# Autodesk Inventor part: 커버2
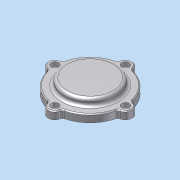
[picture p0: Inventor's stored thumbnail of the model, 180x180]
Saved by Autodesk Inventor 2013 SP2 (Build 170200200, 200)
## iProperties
Company: 한국ATC센터
Created: 2015-03
Part Number: 커버2
Document SubType Name: Modeling
Designer: KYOUNG IL JANG
Density: 1 g/cm^3
Material: 일반
Author: KYOUNG IL JANG
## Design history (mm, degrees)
sketch "스케치1"
  geometry: C1 r 1.621 at (0, 6.75) reference; C2 r 1.621 at (-37, -30.25) reference; C3 r 1.621 at (0, -67.25) reference; C4 r 1.621 at (37, -30.25) reference; C5 r 10 at (0, -30.25) reference; C6 r 12 at (0, -30.25); C7 r 24.5 at (0, -30.25) reference; A1 r 3 centre (-38.77, -20.408) between (-38.239, -23.361) and (-35.862, -21.146) reference; A2 r 7 centre (-37, -30.25) between (-38.239, -23.361) and (-38.239, -37.139) reference; A3 r 3 centre (-38.77, -40.092) between (-35.862, -39.354) and (-38.239, -37.139) reference; A4 r 37 centre (0, -30.25) between (-35.862, -39.354) and (-9.104, -66.113) reference; A5 r 3 centre (-9.842, -69.02) between (-6.889, -68.489) and (-9.104, -66.113) reference; A6 r 7 centre (0, -67.25) between (-6.889, -68.489) and (6.889, -68.489) reference; A7 r 3 centre (9.842, -69.02) between (9.104, -66.112) and (6.889, -68.489) reference; A8 r 37 centre (0, -30.25) between (9.104, -66.112) and (35.863, -39.354) reference; A9 r 3 centre (38.77, -40.092) between (38.239, -37.139) and (35.863, -39.354) reference; A10 r 7 centre (37, -30.25) between (38.239, -37.139) and (38.239, -23.361) reference; A11 r 3 centre (38.77, -20.408) between (35.863, -21.146) and (38.239, -23.361) reference; A12 r 37 centre (0, -30.25) between (35.863, -21.146) and (9.104, 5.612) reference; A13 r 3 centre (9.842, 8.52) between (6.889, 7.989) and (9.104, 5.612) reference; A14 r 7 centre (0, 6.75) between (6.889, 7.989) and (-6.889, 7.989) reference; A15 r 3 centre (-9.842, 8.52) between (-9.104, 5.612) and (-6.889, 7.989) reference; A16 r 37 centre (0, -30.25) between (-9.104, 5.612) and (-35.862, -21.146) reference; 1 further point
  constraints: 1 centre point, 1 coincident
  dimensions: "d2" = 2 radial gap between concentric circles of C6 C5
extrude "돌출1" new body sketch "스케치1" distance "d0" = 8; taper "d1" = 0 deg
sketch "스케치2"
  geometry: C1 r 23.5 at (0, -30.25) reference; C2 r 12 at (0, -30.25) reference; 1 further point
extrude "돌출2" join sketch "스케치2" distance "d4" = 5; taper "d5" = 0 deg
sketch "스케치3"
  geometry: C1 r 23.5 at (0, 0) reference; C2 r 20.5 at (0, 0); 1 further point
  constraints: 1 centre point
  dimensions: "d6" = 3 radial gap between concentric circles of C2 C1
node "작업 평면1"
extrude "돌출3" join sketch "스케치3" stored distance "d7" = 5; taper "d8" = 0 deg
fillet "모깎기1" dims "d9" = 3
sketch "스케치4"
  geometry: C1 r 12 at (0, -30.25) reference; C2 r 27 at (0, -30.25); 1 further point
  constraints: 1 centre point
  dimensions: "d10" = 15 radial gap between concentric circles of C1 C2
extrude "돌출4" join sketch "스케치4" distance "d11" = 7; taper "d12" = 0 deg
fillet "모깎기2" dims "d13" = 3
chamfer "모따기1" distance "d14" = 1; stored, may be unused: second distance "d15" = 2, angle "d16" = 45 deg
node "작업점1"
  node "작업축1"
chamfer "모따기2" distance "d24" = 1; stored, may be unused: second distance "d25" = 2, angle "d26" = 45 deg
hole "구멍6" diameter "d43" = 4.5; stored, may be unused: countersink angle "d47" = 90 deg, drill point angle "d49" = 118 deg; dims "d41" = 10, "d42" = 10, "d44" = 6, "d45" = 8, "d46" = 4.4, "d48" = 8
fillet "모깎기4" dims "d60" = 3
node "솔리드1"
pattern_circular "원형 패턴1" dims angle "d51" = 360 deg
node "참조1"
node "참조2"
